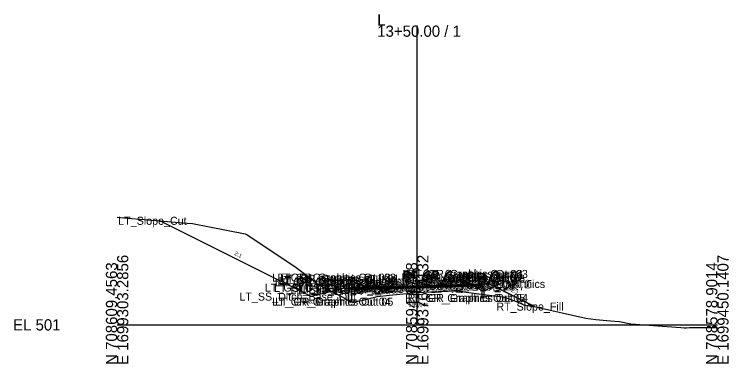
# Model space of a CAD drawing. Extents: x -63 to 1153, y -24 to 9522.
# Drawn here: x -25.7 to 152.8, y 3990.3 to 4077.5 of the extents above; entities that cross this region are included whole.
import ezdxf

# ---------------------------------------------------------------- set-up
doc = ezdxf.new("R2010")
doc.units = 0
for name, color, linetype in [('Default', 7, 'Continuous'), ('Exist Cross Section Cell', 7, 'Continuous'), ('Exist XS Center Line Elevation Label', 7, 'Continuous'), ('Exist XS Ground Line', 7, 'Continuous'), ('Prop CMT DNC', 7, 'Continuous'), ('Prop CMT Guardrail Graphics', 7, 'Continuous'), ('Prop CMT Pvmt Course 1', 7, 'Continuous'), ('Prop CMT Pvmt Course 2', 7, 'Continuous'), ('Prop CMT Pvmt Surface', 7, 'Continuous'), ('Prop CMT Pvmt Surface Overlay', 7, 'Continuous'), ('Prop CMT Pvmt Surface Shoulder', 7, 'Continuous'), ('Prop CMT Shld Paved Course 1', 7, 'Continuous'), ('Prop CMT Shld Paved Course 2', 7, 'Continuous'), ('Prop CMT Slope Grass', 7, 'Continuous'), ('Prop CMT Subgrade Earthwork', 7, 'Continuous'), ('Prop XS Ditch Standard Text', 7, 'Continuous'), ('Prop XS Earthwork Shape', 7, 'Continuous'), ('Prop XS EOT Tick Mark', 7, 'Continuous'), ('Prop XS SE Text', 7, 'Continuous'), ('Prop XS Side Slope Text', 7, 'Continuous')]:
    doc.layers.add(name, color=color, linetype=linetype)

msp = doc.modelspace()

# ---------------------------------------------------------------- linework, layer by layer
at = {"layer": 'Exist Cross Section Cell'}
for p, q in [((75, 4000), (75, 4074.7)), ((0, 4000), (75, 4000)), ((75, 4000), (150, 4000))]:
    msp.add_line(p, q, dxfattribs=at)
at = {"layer": 'Exist XS Ground Line'}
msp.add_lwpolyline([(0, 4026.85), (2.51, 4026.62), (6.79, 4026.31), (17.54, 4025.35), (18.86, 4025.27), (31.99, 4022.71), (32.28, 4022.64), (32.63, 4022.42), (44.76, 4014.29), (49.11, 4011.05), (50.69, 4009.85), (52.6, 4008.91), (57.32, 4006.38), (58.21, 4005.7), (60.26, 4005.95), (61.17, 4006.09), (62.51, 4006.41), (65.02, 4007.09), (68.06, 4007.38), (75, 4008.04), (75.11, 4008.05), (78.38, 4008.22), (84.74, 4008.51), (92.34, 4007.52), (96.43, 4006.99), (97.69, 4006.56), (100.37, 4005.59), (101.59, 4005.01), (104.54, 4004.51), (117.12, 4001.71), (119.65, 4001.34), (123.26, 4000.98), (125.55, 4000.82), (128.39, 4000.22), (140.85, 3999.3), (141.74, 3999.29), (142.3, 3999.29), (143.03, 3999.32), (150, 3999.34)], dxfattribs=at)
at = {"layer": 'Prop CMT Guardrail Graphics'}
for points in [[(57.88, 4005.79), (57.88, 4011.79)], [(57.88, 4011.79), (59.22, 4011.79), (59.49, 4011.49)], [(91.77, 4012.71), (90.44, 4012.71), (90.17, 4012.42)], [(90.17, 4012.42), (90.44, 4012.13)], [(90.44, 4012.13), (90.17, 4011.84)], [(90.17, 4011.84), (90.44, 4011.54), (91.11, 4011.54)], [(91.77, 4006.71), (91.77, 4012.71)], [(59.49, 4010.91), (59.22, 4010.62), (58.55, 4010.62)], [(58.55, 4010.62), (58.55, 4005.79)], [(59.49, 4011.49), (59.22, 4011.2)], [(59.22, 4011.2), (59.49, 4010.91)], [(91.11, 4011.54), (91.11, 4006.71)], [(91.11, 4006.71), (91.77, 4006.71)], [(58.55, 4005.79), (57.88, 4005.79)]]:
    msp.add_lwpolyline(points, dxfattribs=at)
at = {"layer": 'Prop CMT Pvmt Course 1'}
for points in [[(75, 4009.76), (85, 4010.06)], [(85, 4010.06), (85, 4009.81)], [(75, 4009.76), (65, 4009.46)], [(65, 4009.21), (75, 4009.51)], [(65, 4009.46), (65, 4009.21)], [(85, 4009.81), (75, 4009.51)], [(75, 4009.63), (75, 4009.76)], [(75, 4009.63), (75, 4009.76)], [(75, 4009.51), (75, 4009.63), (75, 4009.63)], [(75, 4009.51), (75, 4009.63), (75, 4009.63)]]:
    msp.add_lwpolyline(points, dxfattribs=at)
at = {"layer": 'Prop CMT Pvmt Course 2'}
for points in [[(75, 4009.51), (65, 4009.21)], [(65, 4008.96), (75, 4009.26)], [(65, 4009.21), (65, 4008.96)], [(75, 4009.51), (85, 4009.81)], [(85, 4009.56), (75, 4009.26)], [(75, 4009.26), (75, 4009.51)], [(75, 4009.26), (75, 4009.51)], [(85, 4009.81), (85, 4009.56)]]:
    msp.add_lwpolyline(points, dxfattribs=at)
at = {"layer": 'Prop CMT Pvmt Surface'}
for points in [[(75, 4009.76), (85, 4010.06)], [(75, 4009.76), (65, 4009.46)]]:
    msp.add_lwpolyline(points, dxfattribs=at)
at = {"layer": 'Prop CMT Pvmt Surface Overlay'}
for points in [[(75, 4009.76), (85, 4010.06)], [(75, 4009.76), (65, 4009.46)]]:
    msp.add_lwpolyline(points, dxfattribs=at)
at = {"layer": 'Prop CMT Pvmt Surface Shoulder'}
for points in [[(85, 4010.06), (90.16, 4010.21)], [(65, 4009.46), (59.59, 4009.29)]]:
    msp.add_lwpolyline(points, dxfattribs=at)
at = {"layer": 'Prop CMT Shld Paved Course 1'}
for points in [[(85, 4010.06), (90.16, 4010.21), (90.4, 4009.97)], [(85, 4009.81), (85, 4010.06)], [(90.4, 4009.97), (85, 4009.81)], [(65, 4009.46), (59.59, 4009.29), (59.33, 4009.04)], [(59.33, 4009.04), (65, 4009.21)], [(65, 4009.21), (65, 4009.46)]]:
    msp.add_lwpolyline(points, dxfattribs=at)
at = {"layer": 'Prop CMT Shld Paved Course 2'}
for points in [[(85, 4009.81), (90.4, 4009.97)], [(90.4, 4009.97), (90.4, 4009.97)], [(90.4, 4009.97), (90.65, 4009.73)], [(59.33, 4009.04), (59.07, 4008.78)], [(59.07, 4008.78), (65, 4008.96)], [(65, 4009.21), (59.33, 4009.04)], [(59.33, 4009.04), (59.33, 4009.04)], [(65, 4008.96), (65, 4009.21)], [(85, 4009.56), (85, 4009.81)], [(90.65, 4009.73), (85, 4009.56)]]:
    msp.add_lwpolyline(points, dxfattribs=at)
at = {"layer": 'Prop CMT Slope Grass'}
for points in [[(56.49, 4009.05), (48.49, 4007.05), (10.65, 4025.97)], [(90.16, 4010.21), (90.17, 4010.21)], [(90.16, 4010.21), (93.17, 4010.12)], [(90.17, 4010.21), (93.17, 4010.12)], [(93.17, 4010.12), (104.3, 4004.56)], [(59.49, 4009.29), (56.49, 4009.05)], [(59.59, 4009.29), (59.49, 4009.29)]]:
    msp.add_lwpolyline(points, dxfattribs=at)
at = {"layer": 'Prop CMT Subgrade Earthwork'}
for points in [[(90.65, 4009.73), (91.1, 4010.18)], [(59.07, 4008.78), (58.63, 4009.22)], [(65, 4008.96), (59.07, 4008.78)], [(75, 4009.26), (65, 4008.96)], [(75, 4009.26), (85, 4009.56)], [(85, 4009.56), (90.65, 4009.73)]]:
    msp.add_lwpolyline(points, dxfattribs=at)
at = {"layer": 'Prop XS Earthwork Shape'}
for points in [[(53.66, 4008.34), (48.49, 4007.05), (10.65, 4025.97), (17.54, 4025.35), (18.86, 4025.27), (31.99, 4022.71), (32.28, 4022.64), (32.63, 4022.42), (44.76, 4014.29), (49.11, 4011.05), (50.69, 4009.85), (52.6, 4008.91)], [(68.06, 4007.38), (75, 4008.04), (75.11, 4008.05), (78.38, 4008.22), (84.74, 4008.51), (92.34, 4007.52), (96.43, 4006.99), (97.69, 4006.56), (100.37, 4005.59), (101.59, 4005.01), (104.3, 4004.56), (93.17, 4010.12), (91.1, 4010.18), (90.65, 4009.73), (85, 4009.56), (75, 4009.26), (65, 4008.96), (59.07, 4008.78), (58.63, 4009.22), (56.49, 4009.05), (53.66, 4008.34), (57.32, 4006.38), (58.21, 4005.7), (60.26, 4005.95), (61.17, 4006.09), (62.51, 4006.41), (65.02, 4007.09)]]:
    msp.add_lwpolyline(points, close=True, dxfattribs=at)
at = {"layer": 'Prop XS EOT Tick Mark'}
for points in [[(65, 4009.46), (65, 4010.46)], [(85, 4010.06), (85, 4011.06)]]:
    msp.add_lwpolyline(points, dxfattribs=at)

# ---------------------------------------------------------------- texts
at = {"layer": 'Default'}
msp.add_text('-', height=0.0001, dxfattribs=at).set_placement((0, 4000))
at = {"layer": 'Exist Cross Section Cell'}
for s, p in [('L', (65, 4074.7)), ('13+50.00 / 1', (65, 4071.9)), ('EL 501', (-26, 3998.6))]:
    msp.add_text(s, height=2.8, dxfattribs=at).set_placement(p)
for s, p in [('E 1699303.2856', (2.8, 3990)), ('E 1699376.7132', (77.8, 3990)), ('E 1699450.1407', (152.8, 3990)), ('N 708609.4563', (0, 3990)), ('N 708594.1788', (75, 3990)), ('N 708578.9014', (150, 3990))]:
    msp.add_text(s, height=2.8, rotation=90, dxfattribs=at).set_placement(p)
at = {"layer": 'Exist XS Center Line Elevation Label'}
msp.add_text('509.04', height=1, dxfattribs=at).set_placement((72.86, 4004.51))
at = {"layer": 'Prop CMT DNC'}
for s, p in [('LT_Slope_Cut', (0.28, 4024.97)), ('RT_GR_Graphics Out 02', (71.29, 4011.71)), ('RT_GR_Graphics Out 01', (71.59, 4011.42)), ('RT_GR_Graphics Out 03', (72.62, 4011.71)), ('LT_GR_Graphics Out 03', (38.78, 4010.79)), ('LT_GR_Graphics Out 06', (39.4, 4009.62)), ('LT_GR_Graphics Out 02', (40.11, 4010.79)), ('LT_GR_Graphics Out 09', (40.11, 4010.2)), ('LT_GR_Graphics Out 07', (40.11, 4009.62)), ('LT_GR_Graphics Out 08', (40.38, 4009.91)), ('LT_GR_Graphics Out 01', (40.95, 4010.49)), ('RT_GR_Graphics Out 08', (71.02, 4010.84)), ('RT_GR_Graphics Out 09', (71.29, 4011.13)), ('RT_GR_Graphics Out 07', (71.29, 4010.54)), ('RT_GR_Graphics Out 06', (71.91, 4010.54)), ('RT_TM_OEOT', (75.9, 4010.06)), ('LT_GS_OS_GR_Face_Graphics', (36.94, 4008.29)), ('LT_Sub_Trench_Out_DLT', (39.2, 4008.22)), ('LT_Sub_Trench_Out', (43.28, 4007.78)), ('LT_PS2_Shelf_Out', (45.31, 4008.04)), ('LT_GS_OS_CTL', (45.86, 4008.05)), ('LT_PS2_OEOP', (49.57, 4008.04)), ('LT_PS1_OEOP', (50.39, 4008.29)), ('LT_Sub_OEOT', (55.08, 4007.96)), ('LT_PV2_OEOT', (55.17, 4008.21)), ('LT_PV1_OEOT', (55.74, 4008.46)), ('LT_TM_OEOT', (55.94, 4009.46)), ('RT_PV1_OEEOP_W', (62.94, 4008.63)), ('LT_PV1_OEEOP_W', (62.98, 4008.63)), ('RT_Sub_OEEOP', (64.17, 4008.26)), ('LT_Sub_OEEOP', (64.21, 4008.26)), ('RT_PV2_OEEOP', (64.26, 4008.51)), ('LT_PV2_OEEOP', (64.31, 4008.51)), ('RT_GS_OS_GR_Face_Graphics', (67.58, 4009.21)), ('PV1_PGL_W', (67.58, 4008.63)), ('PV1_PGL', (69.47, 4008.76)), ('RT_Sub_Trench_Out_DLT', (71.62, 4009.18)), ('RT_Sub_Trench_Out', (74.8, 4008.73)), ('RT_Sub_OEOT', (75.03, 4008.56)), ('RT_PV2_OEOT', (75.13, 4008.81)), ('RT_PV1_OEOT', (75.69, 4009.06)), ('RT_PS2_Shelf_Out', (76.34, 4008.97)), ('RT_PS2_OEOP', (80.59, 4008.97)), ('RT_PS1_OEOP', (80.92, 4009.21)), ('RT_GS_OS_CTL', (82.49, 4009.12)), ('LT_SS_Ditch_Base_Out', (30.57, 4006.05)), ('LT_GR_Graphics Out 04', (38.78, 4004.79)), ('LT_GR_Graphics Out 05', (39.45, 4004.79)), ('RT_GR_Graphics Out 05', (71.96, 4005.71)), ('RT_GR_Graphics Out 04', (72.62, 4005.71)), ('RT_Slope_Fill', (94.77, 4003.56))]:
    msp.add_text(s, height=2, dxfattribs=at).set_placement(p)
at = {"layer": 'Prop XS Ditch Standard Text'}
msp.add_text('508.05', height=1, dxfattribs=at).set_placement((46.36, 4005.3))
at = {"layer": 'Prop XS SE Text'}
for p in [(68.22, 4010.55), (78.22, 4010.85)]:
    msp.add_text('0.030', height=1, rotation=1.7184, dxfattribs=at).set_placement(p)
at = {"layer": 'Prop XS Side Slope Text'}
for s, rotation, p in [('2:1', 333.4349, (29.19, 4017.53)), ('4:1', 14.0362, (51.54, 4008.58)), ('2:1', 333.4353, (98.36, 4008.36))]:
    msp.add_text(s, height=1, rotation=rotation, dxfattribs=at).set_placement(p)

doc.saveas('drawing.dxf')
